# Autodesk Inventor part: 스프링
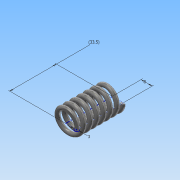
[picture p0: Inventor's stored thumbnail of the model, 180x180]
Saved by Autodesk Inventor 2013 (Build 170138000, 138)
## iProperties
Created: 2019-11
Part Number: 스프링
Material: 스테인리스강, 440C
Document SubType Name: Modeling
Designer: Administrator
Density: 7.75 g/cm^3
Mass: 18.9141 g
Surface Area: 33.0743 cm^2
Volume: 2.44053 cm^3
Author: Administrator
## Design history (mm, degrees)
sketch "스케치1"
  geometry: L1 (0, 0)-(-8, 0); L2 (-8, 0)-(-8, 33.5); L3 (-8, 33.5)-(0, 33.5); L4 (0, 33.5)-(0, 0); C1 r 1.5 at (0, 0)
  constraints: 8 end point, 2 parallel, 1 centre point, 1 coincident, 1 horizontal, 1 perpendicular
  dimensions: "d4" = 8 distance of L2.end L3.end; "d6" = 33.5 distance of L1.end L2.end (derived); "d7" = 3 diameter of C1
feature "코일1" pitch "d8" = 10; turns "d10" = 7; dims "d9" = 33.5 (= d6), "d11" = 0, angle "d12" = 90 deg, angle "d13" = 90 deg, "d14" = 0, "d15" = 0
sketch "스케치2"
  geometry: L1 (-40.508, 0)-(32.701, 0); L2 (32.701, 0)-(32.701, 33.5); L3 (32.701, 33.5)-(-40.508, 33.5); L4 (-40.508, 33.5)-(-40.508, 0); 1 further point
  constraints: 8 end point, 2 parallel, 1 horizontal, 1 perpendicular
  dimensions: "d16" = 0 distance from line of point (0, 0) L1; "d17" = 33.5 distance of L1.end L2.end (= d6)
extrude "돌출1" sketch "스케치2" stored distance "d18" = 40; taper "d19" = 0 deg
node "솔리드1"
